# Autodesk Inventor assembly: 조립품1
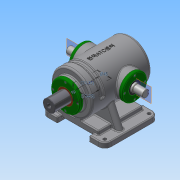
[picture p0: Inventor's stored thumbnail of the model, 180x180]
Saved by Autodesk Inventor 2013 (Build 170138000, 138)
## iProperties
Created: 2018-06
Part Number: 조립품1
Document SubType Name: Assembly
Designer: Administrator
Author: Administrator
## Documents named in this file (13)
- C:\Users\Administrator\Desktop\380628V1015\조립품1.iam
- C:\Users\Administrator\Desktop\380628V1015\본체.ipt
- C:\Users\Administrator\Desktop\380628V1015\가변 스프링.ipt
- C:\Users\Administrator\Desktop\380628V1015\베어링 6205.ipt
- 베어링 6205.ipt
- C:\Users\Administrator\Desktop\380628V1015\볼트 M4.ipt
- C:\Users\Administrator\Desktop\380628V1015\부시.ipt
- C:\Users\Administrator\Desktop\380628V1015\슬라이드 커버.ipt
- C:\Users\Administrator\Desktop\380628V1015\슬라이드.ipt
- C:\Users\Administrator\Desktop\380628V1015\오일실.ipt
- 오일실.ipt
- C:\Users\Administrator\Desktop\380628V1015\축 커버.ipt
- C:\Users\Administrator\Desktop\380628V1015\편심축.ipt
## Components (1 placed, 1 different names)
1. 가변 스프링:1
